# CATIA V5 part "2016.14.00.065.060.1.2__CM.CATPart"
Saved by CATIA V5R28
Part number: 2016.14.00.065.060.1.2__CM
Property "id_number": "2016.14.00.065.060.1.2"
Publications: "Absolute Axis System", "driver", "slider", "base", "cam diagram"
Bounding box of the stored display mesh (mm): x -60 to 190, y -65 to 65, z 0 to 220
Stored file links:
  N:\B2\Normteile\K\2016\11-14\006\cm\2016.14.00.065.060.1.2__CM.CATPart
  H:\CAD_Startmodelle\Tests\fill-in_PRT-SL_TEMPLATE.xlsx
  H:\CAD_Startmodelle\V5-R24\R24_TEMPLATE_PRT_FIBRO_CAM_TECNOLOGIES_INDEX.xlsx
  H:\z_Einordnen\170511__Anfrage_TK_HN\170511__CC01_TKHN.CATPart
  N:\B2\Normteile\K\2016\9xxx\2016.9024.1705.001\Entwurf_\170511__CC01_TKHN.CATPart
  N:\B2\Normteile\K\2016\9xxx\2016.9024.1707.006\Konstruktion\2016.9024.1707.006__HP__CUSTOMIZED_CAM_CM.CATPart
  N:\B2\Normteile\K\2016\9xxx\2016.9024.1707.005\Konstruktion\2016.9024.1707.005__HP__CUSTOMIZED_CAM_CM.CATPart
  N:\B2\Normteile\K\2016\9xxx\2016.9024.1707.008\Konstruktion\2016.9024.1707.008__HP__CUSTOMIZED_CAM_CM.CATPart
  N:\B2\Normteile\K\2016\9xxx\2016.9024.1707.009\Konstruktion\2016.9024.1707.009__HP__CUSTOMIZED_CAM_CM.CATPart
  N:\B2\Normteile\K\2016\9xxx\2016.9024.1707.010\Konstruktion\2016.9024.1707.010__HP__CUSTOMIZED_CAM_CM.CATPart
  N:\B2\Normteile\K\2016\9xxx\2016.9024.1708.002\Konstruktion\2016.9024.1708.002__HP__CUSTOMIZED_CAM_CM.CATPart
  N:\B2\Normteile\K\2016\9xxx\2016.9024.1802.001\Konstruktion\2016.9024.1802.001__HP__CUSTOMIZED_CAM_CM.CATPart
  N:\B2\Normteile\K\2016\9xxx\2016.9024.1802.002\Konstruktion\2016.9024.1802.002__HP__CUSTOMIZED_CAM_CM.CATPart
  N:\B2\Normteile\K\2016\9xxx\2016.9024.1811.003\Konstruktion\2016.9024.1811.003__HP__CUSTOMIZED_CAM_CM.CATPart
  N:\B2\Normteile\K\2016\9xxx\2016.9015.1811.001\Konstruktion\am\2016.9015.1811.001__AM__FCC_HV_DMC_0125-00.CATPart
  N:\B2\Normteile\K\2016\9xxx\2016.9024.1811.009\Konstruktion\2016.9024.1811.009__HP__CUSTOMIZED_CAM_CM.CATPart
  N:\B2\Normteile\K\2016\9xxx\2016.9024.1911.002\Konstruktion\am\2016.9024.1911.002__AM__CUSTOMIZED_CAM_CM.CATPart
  N:\B2\Normteile\K\2016\9xxx\2016.9024.2002.006\Konstruktion\2016.9024.2002.006__AM.CATPart
  N:\B2\Normteile\K\2016\9xxx\2016.9024.2004.001\Konstruktion\2016.9024.2004.001__AM__FCC_HV_CAEC_0260-45.CATPart
  N:\B2\Normteile\K\2016\9xxx\2016.9024.2006.002\Konstruktion\2016.9024.2006.002__AM__FCC_HV_CAEC_0260-40.CATPart
  N:\B2\Normteile\K\2016\9xxx\2016.9024.2006.005\Konstruktion\am\2016.9024.2006.005__AM__CFCC_HV_AEPC_0080-65.CATPart
  N:\B2\Normteile\K\2016\9xxx\2016.9024.2006.004\Konstruktion\am\2016.9024.2006.004__AM__CFCC_HV_AEC_0210-35.CATPart
  N:\B2\Normteile\K\2016\9xxx\2016.9026.2006.001\Konstruktion\am\2016.9026.2006.001__AM__FCC_LV_CAEC_0180-40.CATPart
  N:\B2\Normteile\K\2016\9xxx\2016.9015.2007.001\Konstruktion\am\2016.9015.2007.001__AM__FCC_HV_CDMPC_0090-00.CATPart
  N:\B2\Normteile\K\2016\9xxx\2016.9024.2005.001\Konstruktion\am\2016.9024.2005.001__AM__CFCC_HV_AEPC_1400-70.CATPart
  N:\B2\Normteile\K\2016\9xxx\2016.9024.2007.004\Konstruktion\am\2016.9024.2007.004__AM__CFCC_HV_AEC_1250-80.CATPart
  N:\B2\Normteile\K\2016\11-14\005\2016.11.00.052.040.1.02__AS__DIE_MOUNT_CAM__W52_A0_S40.CATProduct
  N:\B2\Normteile\K\2016\11-14\cm\005\catia\2016.11.00.052.025.1.2__CM.CATPart
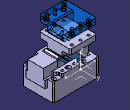
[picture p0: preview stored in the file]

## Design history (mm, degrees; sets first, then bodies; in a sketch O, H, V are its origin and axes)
Parameters
  group "process_parameters"
    modeltype = ""
    stocklist = ""
    id_number = "2016.14.00.065.060.1.2"
    id_number_rough_part = ""
    revision_index = ""
    revision_date = ""
    revision_description = ""
    category = ""
    material = ""
    manufacturing_information = ""
    standard = ""
  group "release_parameters_startmodel"
    sm_revision_index = "2016_00" {design table}
    sm_revision_date = "20.08.2016" {design table}
    sm_revision_name = "Meyer" {design table}
    sm_revision_description = "new part template FIBRO cam tecnologies" {design table}
AxisSystem1: origin (0, 0, 0), X (1, 0, 0), Y (0, 1, 0), Z (0, 0, 1)
Set1 "reference elements"
  Sketch1 "cam diagram" on ZX plane of AxisSystem1, origin (0, 0, 0), H (-1, 0, 0), V (0, 0, 1)
    line L1 (0, 0) -> (60, 0)
    line L2 (60, 0) -> (0, 60)
    point P2 (0, 60)
    line L3 (0, 60) -> (0, 0)
    length L1 = 60
    angle H L2 = 45
    horizontal: L1 H
    coincidence: P2 V
    vertical: L3 V
Body1 "finished_part" (main body)
  Body2 "rough_part"
  Add1 "rough_part": tool Body2
  Body3 "milling operations"
  Remove1 "milling operations": tool Body3
  Body4 "drilling operations"
  Remove2 "drilling operations": tool Body4
Body5 "driver"
  Solid1: solid without history
Body6 "slider"
  Solid2: solid without history
Body7 "base"
  Solid3: solid without history
Body8 "opened position"
  Body9 "slider"
    Body10 "slider"
      Solid4: linked copy from another document
    Assemble1: tool Body10
    Translate1: FirstPoint vertex [element of Sketch1 | element of Sketch1], SecondPoint vertex [element of Sketch1 | element of Sketch1], ToTransfor Assemble1
  Assemble2: tool Body9
  Body11 "driver"
    Body12 "driver"
      Solid5: linked copy from another document
    Assemble3: tool Body12
    Translate2: FirstPoint vertex [element of Sketch1 | element of Sketch1], SecondPoint vertex [element of Sketch1 | element of Sketch1], ToTransfor Assemble3
  Assemble4: tool Body11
